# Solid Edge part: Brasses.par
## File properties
Accuracy: 0.990
Author: CADCIM
Template: iso part.par
Last saved by: CADCIM
Revision: 14
Application: Solid Edge
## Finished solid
Body 1: solid body, 16 faces, 18 edges, 0 vertices.
  Faces by surface: cylinder 9, plane 7
  Edges by curve: circle 14, intersection 4
Bounding box of the edges (mm): 78.000 x 64.000 x 64.000, from (-39, -32, -32) to (39, 32, 32).
Cylindrical faces by radius (mm): R3 x2, R4 x1, R16 x1, R22 x1, R24 x2, R32 x2
Planar faces by outward normal: +x 3, +z 1, -x 3
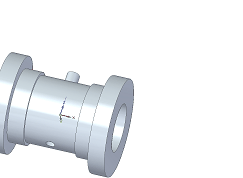
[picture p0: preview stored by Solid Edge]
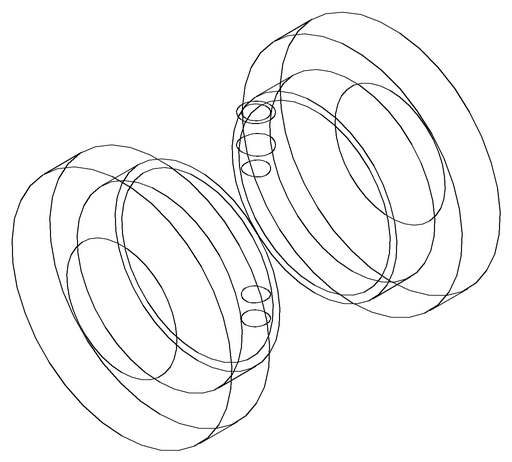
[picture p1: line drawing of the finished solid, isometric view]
